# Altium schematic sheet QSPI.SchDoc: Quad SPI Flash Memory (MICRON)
size A4; Date: 25-FEB-2015; Author: A.B; CompanyName: STMicroelectronics; Address1: 12, Rue Jules HOROWITZ; Address2: 38019 Grenoble; Address3: FRANCE; DocumentNumber: MB1191; Revision: B-02; SheetNumber: 7; SheetTotal: 14; Project: STM32F746G-DISCO
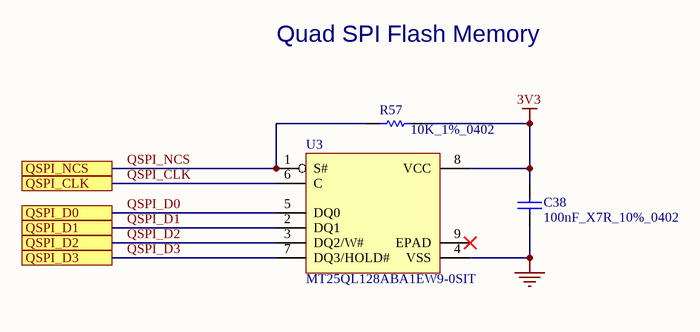
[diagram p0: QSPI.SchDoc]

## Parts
C38  100nF_X7R_10%_0402  [0402C]
R57  10K_1%_0402  [0402R]
U3  MT25QL128ABA1EW9-0SIT  [W-PDFN-8_8X6_P127]

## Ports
QSPI_CLK, QSPI_D0, QSPI_D1, QSPI_D2, QSPI_D3, QSPI_NCS

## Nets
3V3: C38.2 R57.2 U3.8(VCC)
GND: C38.1 U3.4(VSS)
QSPI_CLK: U3.6(C) ; port QSPI_CLK
QSPI_D0: U3.5(DQ0) ; port QSPI_D0
QSPI_D1: U3.2(DQ1) ; port QSPI_D1
QSPI_D2: U3.3(DQ2/W#) ; port QSPI_D2
QSPI_D3: U3.7(DQ3/HOLD#) ; port QSPI_D3
QSPI_NCS: R57.1 U3.1(S#) ; port QSPI_NCS

Not connected (* = marked no-connect by the designer): U3 9(EPAD)*

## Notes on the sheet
- Quad SPI Flash Memory

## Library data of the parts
C38 = Cap_100nF_X7R_10%_0402: Capacitor,100nF,16V,X7R,10%,0402,YAGEO; Manuf_Part_1: CC0402KRX7R7BB104
R57 = Res_10K_1%_0402: Resistor,10K,0402,1%,YAGEO; Manuf_Part_1: RC0402FR-0710KL
U3 = MT25QL128ABA1EW9-0SIT: 128Mb, 3V, Multiple I/O Serial Flash Memory, Quad/Dual; Manuf_1: MICRON; ECCN_US/EU: 3A991/NEC; Provided: ST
